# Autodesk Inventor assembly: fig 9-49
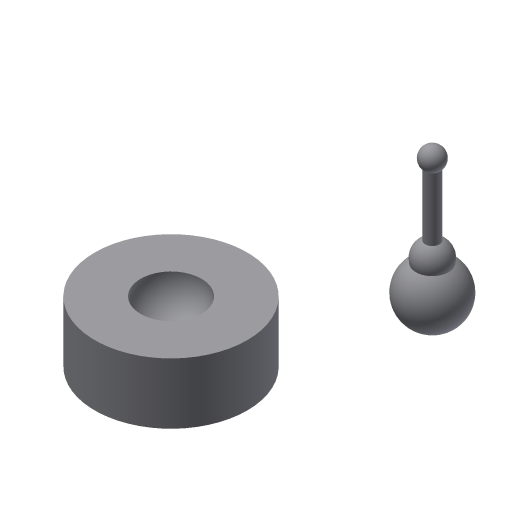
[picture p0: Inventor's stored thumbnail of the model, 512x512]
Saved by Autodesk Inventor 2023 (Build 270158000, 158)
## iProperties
Created: 2013-07
Part Number: fig 9-49
Document SubType Name: Assembly
Designer: CADCIM
Author: CADCIM
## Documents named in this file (3)
- D:\PROJECTS\Project 2022\Autodesk Inventor For Professional 2023\RESOURCES INVENTOR 2023\RESOURCES INVENTOR 2023\Inventor_2023_Part\Inventor_2023_Part\c09_Inv_2023_prt\fig 9-50.iam
- D:\PROJECTS\Project 2022\Autodesk Inventor For Professional 2023\RESOURCES INVENTOR 2023\RESOURCES INVENTOR 2023\Inventor_2023_Part\Inventor_2023_Part\c09_Inv_2023_prt\19.ipt
- D:\PROJECTS\Project 2022\Autodesk Inventor For Professional 2023\RESOURCES INVENTOR 2023\RESOURCES INVENTOR 2023\Inventor_2023_Part\Inventor_2023_Part\c09_Inv_2023_prt\20.ipt
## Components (2 placed, 2 different names)
1. 19:1
2. 20:2
